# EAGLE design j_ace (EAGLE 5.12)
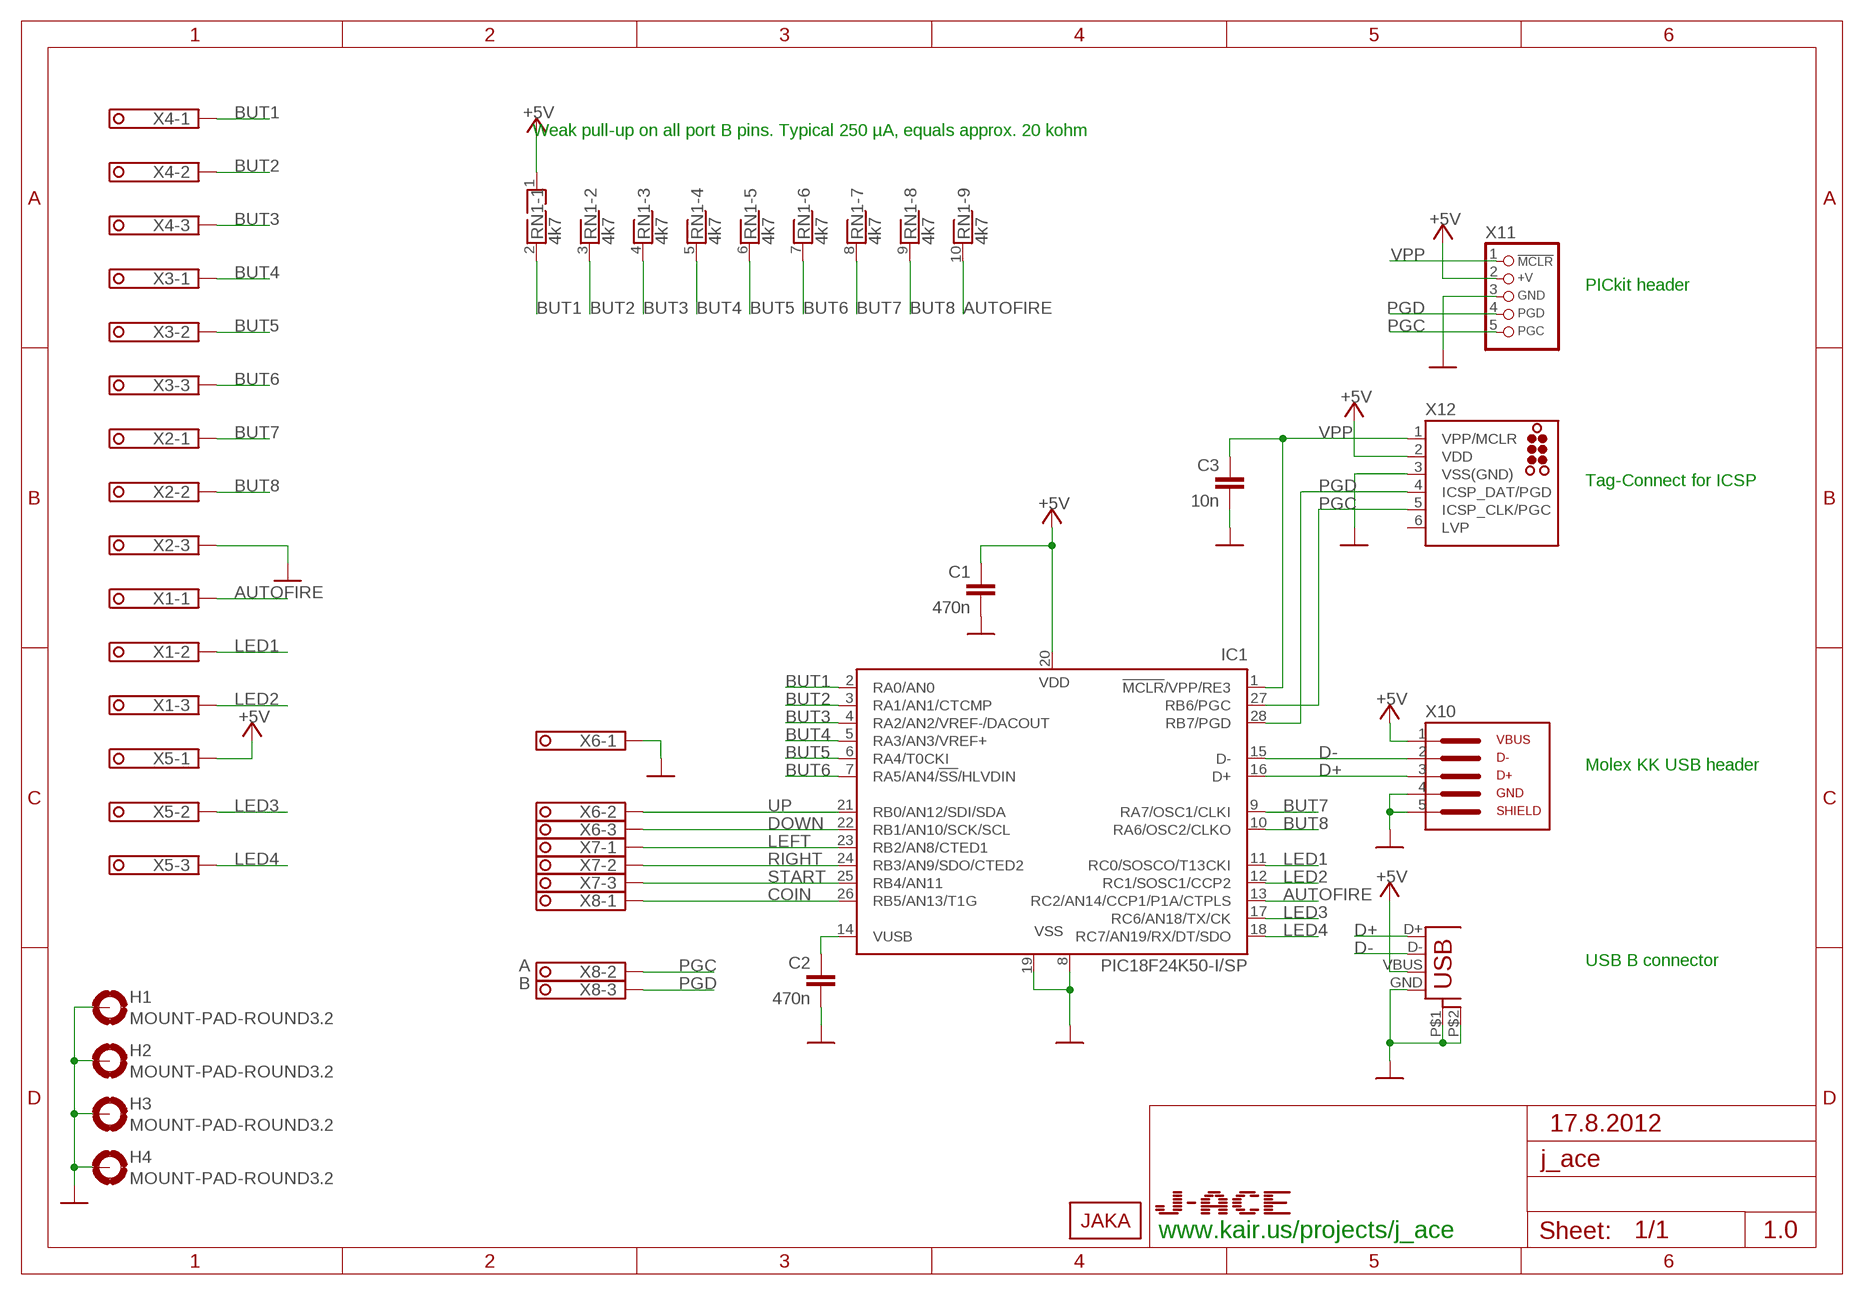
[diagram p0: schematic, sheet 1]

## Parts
C1  470n  C-EU050-024X044  [C050-024X044]
C2  470n  C-EU050-024X044  [C050-024X044]
C3  10n  C-EU050-024X044  [C050-024X044]
H1  MOUNT-PAD-ROUND3.2  [3,2-PAD]
H2  MOUNT-PAD-ROUND3.2  [3,2-PAD]
H3  MOUNT-PAD-ROUND3.2  [3,2-PAD]
H4  MOUNT-PAD-ROUND3.2  [3,2-PAD]
IC1  PIC18F24K50-I/SP  PIC18F2X50-I/SP  [DIL28-3]
LOGO1  J-ACE_LOGO_033  [J_ACE_LOGO_SILK_033]
RN1  4k7  RNX9  [RN-10]
U$1  JAKA_LOGO_SILK_NANO  [JAKA_SILK_NANO]
X1  1984620  [1984620]
X2  1984620  [1984620]
X3  1984620  [1984620]
X4  1984620  [1984620]
X5  1984620  [1984620]
X6  1984620  [1984620]
X7  1984620  [1984620]
X8  1984620  [1984620]
X9  USB_B_PTH  [SPARKFUN_USB-B-PTH]
X10  22-05-3051_USB_HEADER  [22-05-3051]
X11  CON_HEADER_PRG_PIC_ICSPSTAG  [HEADER_PRG_1X05_STAGGERED]
X12  TC2030-MCP-NL-JKA  [TC2030-MCP-NL-JKA]

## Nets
+5V [power]: C1.1 IC1.20(VDD) RN1.1 X5.1 X9.VBUS X10.1 X11.2(+V) X12.2(VDD)
AUTOFIRE: IC1.13(RC2/AN14/CCP1/P1A/CTPLS) RN1.10 X1.1
BUT1: IC1.2(RA0/AN0) RN1.2 X4.1
BUT2: IC1.3(RA1/AN1/CTCMP) RN1.3 X4.2
BUT3: IC1.4(RA2/AN2/VREF-/DACOUT) RN1.4 X4.3
BUT4: IC1.5(RA3/AN3/VREF+) RN1.5 X3.1
BUT5: IC1.6(RA4/T0CKI) RN1.6 X3.2
BUT6: IC1.7(RA5/AN4/!SS!/HLVDIN) RN1.7 X3.3
BUT7: IC1.9(RA7/OSC1/CLKI) RN1.8 X2.1
BUT8: IC1.10(RA6/OSC2/CLKO) RN1.9 X2.2
COIN: IC1.26(RB5/AN13/T1G) X8.1
D+ [USB]: IC1.16(D+) X9.D+ X10.3
D- [USB]: IC1.15(D-) X9.D- X10.2
DOWN: IC1.22(RB1/AN10/SCK/SCL) X6.3
GND [power]: C1.2 C2.2 C3.2 H1.B3,2(MOUNT) H2.B3,2(MOUNT) H3.B3,2(MOUNT) H4.B3,2(MOUNT) IC1.8(VSS) IC1.19(VSS) X2.3 X6.1 X9.GND X9.P$1(SHIELD) X9.P$2(SHIELD1) X10.4 X10.5 X11.3(GND) X12.3(VSS(GND))
LED1: IC1.11(RC0/SOSCO/T13CKI) X1.2
LED2: IC1.12(RC1/SOSC1/CCP2) X1.3
LED3: IC1.17(RC6/AN18/TX/CK) X5.2
LED4: IC1.18(RC7/AN19/RX/DT/SDO) X5.3
LEFT: IC1.23(RB2/AN8/CTED1) X7.1
N$3: C2.1 IC1.14(VUSB)
PGC: IC1.27(RB6/PGC) X8.2 X11.5(PGC) X12.5(ICSP_CLK/PGC)
PGD: IC1.28(RB7/PGD) X8.3 X11.4(PGD) X12.4(ICSP_DAT/PGD)
RIGHT: IC1.24(RB3/AN9/SDO/CTED2) X7.2
START: IC1.25(RB4/AN11) X7.3
UP: IC1.21(RB0/AN12/SDI/SDA) X6.2
VPP: C3.1 IC1.1(!MCLR!/VPP/RE3) X11.1(/MCLR) X12.1(VPP/MCLR)
Unconnected: X12.6(LVP)

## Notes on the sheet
- Weak pull-up on all port B pins. Typical 250 µA, equals approx. 20 kohm
- PICkit header
- Tag-Connect for ICSP
- Molex KK USB header
- USB B connector
- A
- B
- 17.8.2012
- www.kair.us/projects/j_ace | 1.0

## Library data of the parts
C1-C3 = dual_atari:C-EU: CAPACITOR, European symbol
H1-H4 = omat:MOUNT-PAD-ROUND: MOUNTING PAD, round
IC1 = dual_atari:PIC18F2X50
LOGO1 = omat:J-ACE_LOGO
RN1 = omat:RNX9: RESISTOR NETWORK
U$1 = dual_atari:JAKA_LOGO
X1-X8 = omat:1984620: MKDS 1/ 3-3,5 Printklemme Nennstrom: 10 A Bemessungsspannung: 160 V Raster: 3,5 mm Polzahl: 3 Montageart: Löten Anschlussart: Schraubanschluss Anschlussrichtung vom Leiter zur Platine: 0° Source: http://eshop.phoenixcontact.com .. 1751251.pdf; OC_FARNELL: unknown; OC_NEWARK: unknown
X9 = dual_atari:USB_B_PTH
X10 = omat:22-05-3051_USB_HEADER
X11 = omat:CON_HEADER_PRG_PIC_ICSP: 5-pin PIC In Circuit Serial Programming header
X12 = dual_atari:TC2030: TAG-CONNECT ISP Connector Manufacturer: Tag-Connect Cable for easy In-Circuit PCB Programming. Designed for Microchip ICD2, suitable for many others. Two variants - one "with legs" (for hads-free fit on PCB) and another "without legs" for quick programming. PADDescription 1MCLR/Vpp 2Vdd 3GND 4PGD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

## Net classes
0 default: width 0.3 mm, drill 0.6 mm, clearance 0.35 mm
1 USB: width 1.2 mm, drill 0.6 mm, clearance 0.35 mm
2 power: width 1 mm, drill 0.6 mm, clearance 0.35 mm

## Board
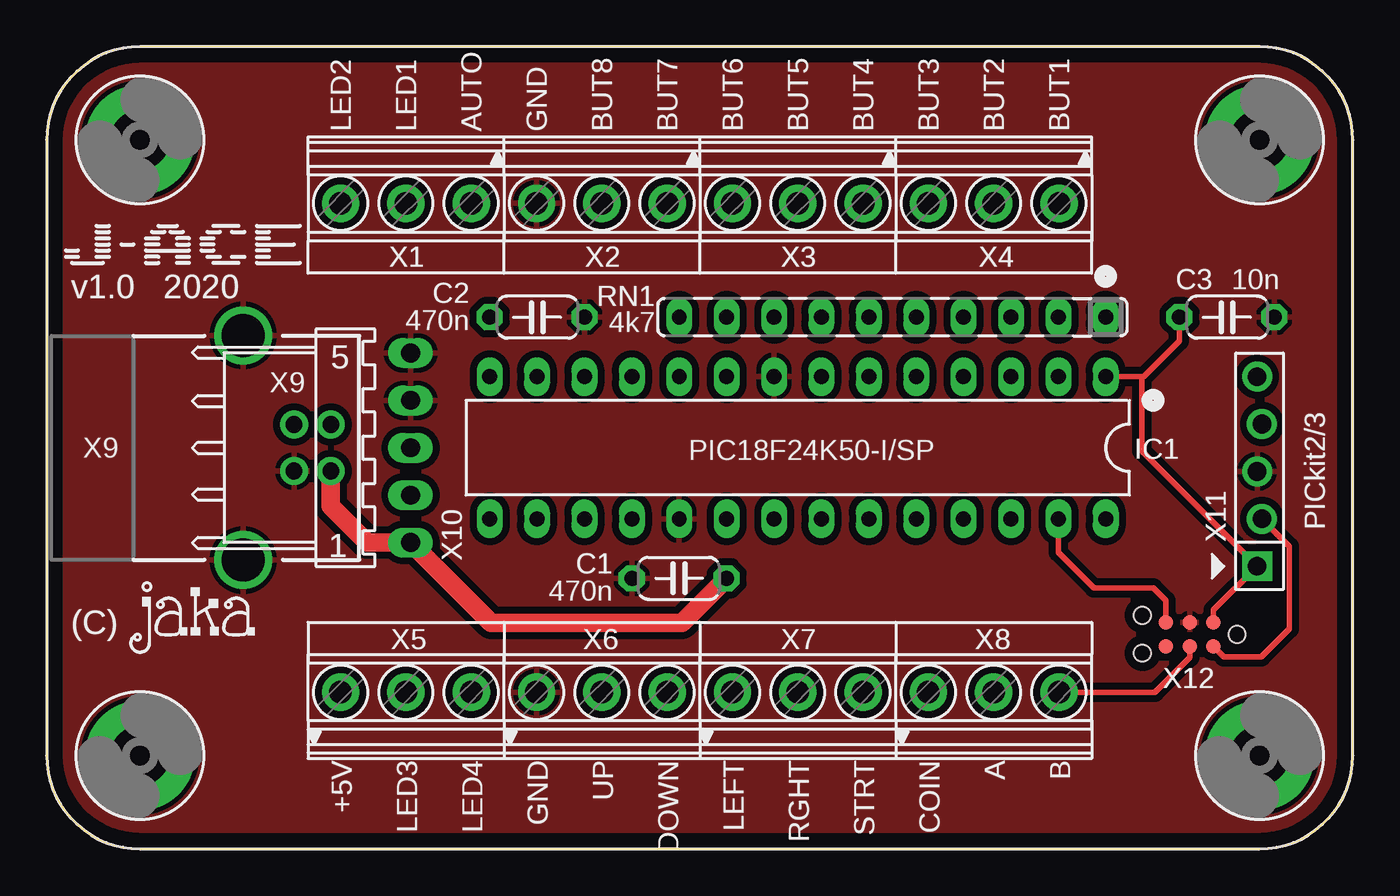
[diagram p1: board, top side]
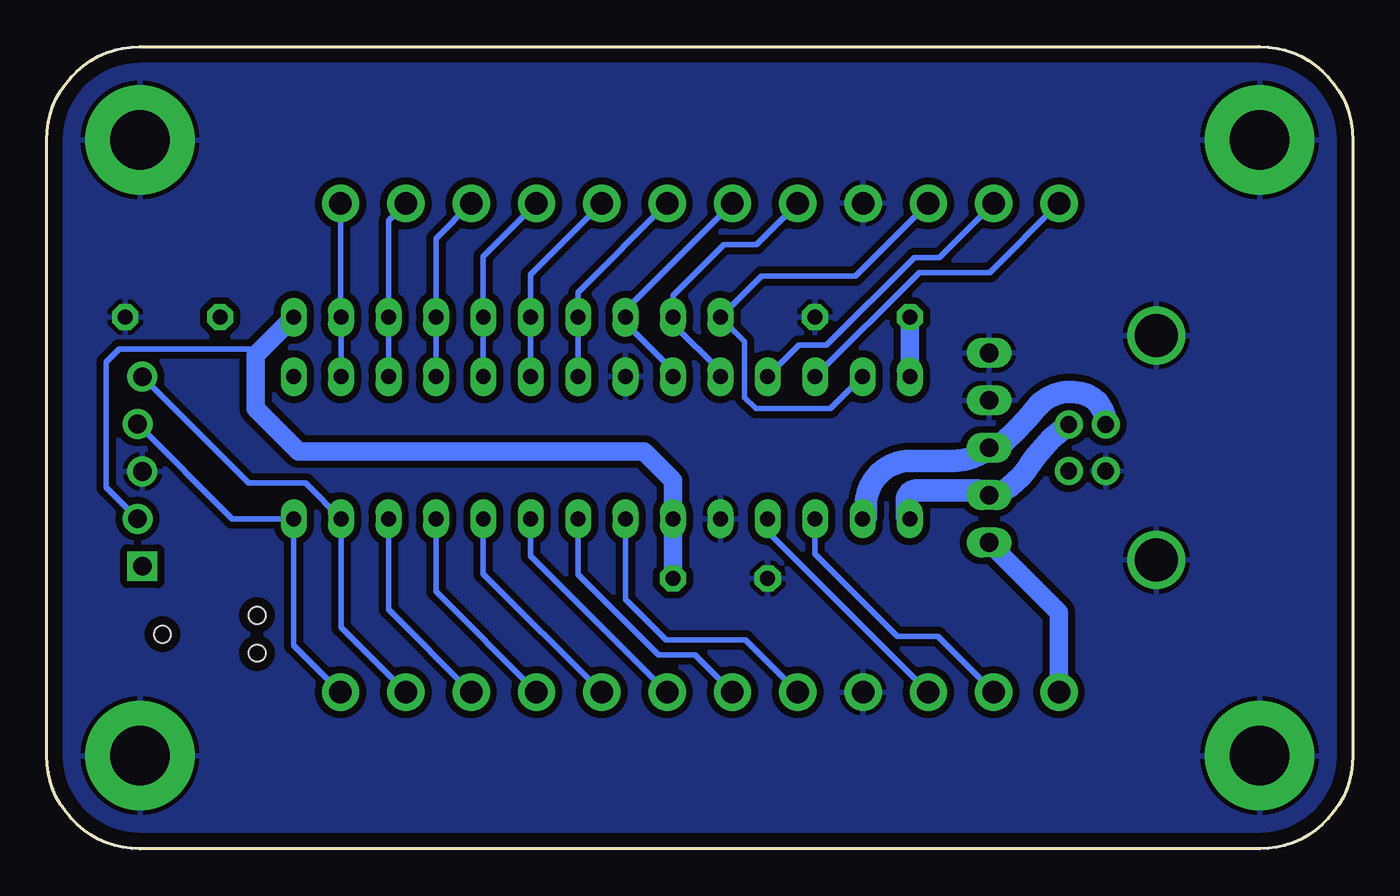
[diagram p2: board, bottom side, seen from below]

Size 70 x 43 mm. Coordinates in mm from the lower left corner, seen from the top.
Outline: 5,43 arc90 0,38 0,5 arc90 5,0 65,0 arc90 70,5 70,38 arc90 65,43 5,43
Copper layers (1*16): Top 0.035mm / dielectric 1.1mm / Bottom 0.035mm
Design rules "ITEADstudio_DRC *": minimum track width 0.3mm, minimum drill 0.6mm, track to track 0.35mm, track to pad 0.35mm, pad to pad 0.35mm, via to via 0.35mm, smd to smd 0mil, copper to edge 0.5mm, drill to drill 0.25mm, minimum pad ring 0.3mm, minimum via ring 0.3mm, stop-mask expansion 2mil, vias tented up to drill 100mil, thermal gap 10mil
tRestrict: area 3.6,3.6 to 6.4,6.4; area 63.6,3.6 to 66.4,6.4; area 3.6,36.6 to 6.4,39.4; area 63.6,36.6 to 66.4,39.4
bRestrict: area 3.6,3.6 to 6.4,6.4; area 63.6,3.6 to 66.4,6.4; area 3.6,36.6 to 6.4,39.4; area 63.6,36.6 to 66.4,39.4

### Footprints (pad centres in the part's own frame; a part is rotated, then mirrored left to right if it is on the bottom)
C050-024X044 = drill 0.8 octagon: 1 -2.54,0; 2 2.54,0
3,2-PAD = drill 3.2 pad 5.842 round: B3,2 0,0
DIL28-3 = drill 0.8 long: 1 -16.51,-3.81; 2 -13.97,-3.81; 3 -11.43,-3.81; 4 -8.89,-3.81; 5 -6.35,-3.81; 6 -3.81,-3.81; 7 -1.27,-3.81; 8 1.27,-3.81; 9 3.81,-3.81; 10 6.35,-3.81; 11 8.89,-3.81; 12 11.43,-3.81; 13 13.97,-3.81; 14 16.51,-3.81; 15 16.51,3.81; 16 13.97,3.81; 17 11.43,3.81; 18 8.89,3.81; 19 6.35,3.81; 20 3.81,3.81; 21 1.27,3.81; 22 -1.27,3.81; 23 -3.81,3.81; 24 -6.35,3.81; 25 -8.89,3.81; 26 -11.43,3.81; 27 -13.97,3.81; 28 -16.51,3.81
RN-10 = drill 0.8 long: 1 -11.43,0; 2 -8.89,0; 3 -6.35,0; 4 -3.81,0; 5 -1.27,0; 6 1.27,0; 7 3.81,0; 8 6.35,0; 9 8.89,0; 10 11.43,0
1984620 = drill 1.2 pad 2 round: 1 -3.5,-0.1; 2 0,-0.1; 3 3.5,-0.1
SPARKFUN_USB-B-PTH = drill 0.9 round: D+ 0,1.25; D- 1.981,1.25; GND 0,-1.25; VBUS 1.981,-1.25 | drill 2.3 round: P$1 -2.718,-6.02; P$2 -2.718,6.02
22-05-3051 = drill 1 long: 1 5.08,0; 2 2.54,0; 3 0,0; 4 -2.54,0; 5 -5.08,0
HEADER_PRG_1X05_STAGGERED = drill 1 square: 1 -5.08,0.127 | drill 1 round: 2 -2.54,-0.127; 3 0,0.127; 4 2.54,-0.127; 5 5.08,0.127
TC2030-MCP-NL-JKA = smd 0.787 x 0.787: 1 1.27,-0.635; 2 1.27,0.635; 3 2.54,-0.635; 4 2.54,0.635; 5 3.81,-0.635; 6 3.81,0.635 | hole 0.9: 0,0; 5.08,-1.016; 5.08,1.016

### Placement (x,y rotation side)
C1  33.9,14.5 180 top
C2  26.28,28.5 0 top
C3  63.25,28.5 0 top
H1  65,5 0 top
H2  5,5 0 top
H3  5,38 0 top
H4  65,38 0 top
IC1  40.25,21.5 180 top
LOGO1  7.3,32.4 0 top
RN1  45.33,28.5 180 top
U$1  7.8,12.4 0 top
U$2  [A5L-LOC]  not placed on the board
X1  19.25,34.5 180 top
X2  29.75,34.5 180 top
X3  40.25,34.5 180 top
X4  50.75,34.5 180 top
X5  19.25,8.5 0 top
X6  29.75,8.5 0 top
X7  40.25,8.5 0 top
X8  50.75,8.5 0 top
X9  13.25,21.5 0 top
X10  19.5,21.5 270 top
X11  65,20.23 90 top
X12  63.8,11.5 180 top

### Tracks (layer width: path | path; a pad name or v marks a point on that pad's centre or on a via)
+5V
  Top 0.3: X12.2 63.09,10.3 65.1,10.3 66.6,11.8 66.6,16.22 X11.2
  Top 1: X9.VBUS 15.23,18.37 17.18,16.42 X10.1 23.82,12.1 34.04,12.1 C1.1
  Bottom 0.3: X11.2 66.8,19.36 66.8,26.1 66.1,26.8 59.14,26.8 58.8,26.46
  Bottom 1: X10.1 15.75,12.67 X5.1 | C1.1 IC1.20 36.44,19.74 38,21.3 56.5,21.3 58.8,23.6 58.8,26.46 RN1.1
AUTOFIRE
  Bottom 0.3: IC1.13 27.99,23.6 32,23.6 32.6,24.2 32.6,27.2 RN1.10 31.7,30.7 26.65,30.7 X1.1
BUT1
  Bottom 0.3: IC1.2 54.22,28 | 54.22,28 RN1.2 | X4.1 54.25,28.03 54.22,28
BUT2
  Bottom 0.3: IC1.3 RN1.3 51.68,33.67 X4.2
BUT3
  Bottom 0.3: IC1.4 RN1.4 49.14,32.71 X4.3
BUT4
  Bottom 0.3: IC1.5 RN1.5 46.6,31.75 X3.1
BUT5
  Bottom 0.3: IC1.6 RN1.6 44.06,30.79 X3.2
BUT6
  Bottom 0.3: IC1.7 RN1.7 41.52,29.83 X3.3
BUT7
  Bottom 0.3: IC1.9 36.44,25.64 38.98,28.18 RN1.8 38.98,28.87 X2.1
BUT8
  Bottom 0.3: IC1.10 33.9,25.6 36.44,28.14 RN1.9 36.44,29.66 33.7,32.4 31.95,32.4 X2.2
COIN
  Bottom 0.3: IC1.26 51.68,12.83 X8.1
D+
  Bottom 1.2: IC1.16 arc-45 26.16,17.74 26.1,17.8 26.1,18.4 arc90 23.7,20.8 21.4,20.8 arc-40 X10.3 arc-45 18.7,21.8 arc-7 16.9,23.7 arc49 15.2,24.5 arc29 14,24.2 arc59 X9.D+
D-
  Bottom 1.2: IC1.15 arc90 23.9,17.85 23.9,18.7 arc90 23.4,19.2 20.1,19.2 arc-90 19.86,18.96 X10.2 arc-33 18.7,19.2 arc-23 17.3,20.6 arc21 X9.D-
DOWN
  Bottom 0.3: IC1.22 41.52,14.72 37.2,10.4 35.25,10.4 X6.3
GND
  pour Bottom (isolate 0.37): 1,5 arc90 5,1 65,1 arc90 69,5 69,38 arc90 65,42 5,42 arc90 1,38
  pour Top (isolate 0.37): 1,5 arc90 5,1 65,1 arc90 69,5 69,38 arc90 65,42 5,42 arc90 1,38
LED1
  Bottom 0.3: IC1.11 29.67,27 28.2,27 23.5,31.7 22.15,31.7 X1.2
LED2
  Bottom 0.3: IC1.12 23.23,30.9 19.45,30.9 X1.3
LED3
  Bottom 0.3: IC1.17 28.82,15.82 24.4,11.4 22.25,11.4 X5.2
LED4
  Bottom 0.3: IC1.18 31.36,17.01 X5.3
LEFT
  Bottom 0.3: IC1.23 44.06,15.71 X7.1
N$3
  Bottom 1: IC1.14 C2.1
PGC
  Top 0.3: X12.5 59.99,13.31 59.3,14 56.12,14 54.22,15.9 IC1.27
  Bottom 0.3: X8.2 54.22,11.87 IC1.27 56.13,19.6 59.16,19.6 X11.5
PGD
  Top 0.3: X12.4 61.26,10.26 59.4,8.4 X8.3
  Bottom 0.3: X8.3 56.76,10.91 IC1.28 60.05,17.69 X11.4
RIGHT
  Bottom 0.3: IC1.24 46.6,14.75 X7.2
START
  Bottom 0.3: IC1.25 49.14,13.79 X7.3
UP
  Bottom 0.3: IC1.21 38.98,13.38 36.8,11.2 32.55,11.2 X6.2
VPP
  Top 0.3: X12.1 62.53,12.81 X11.1 58.7,21.32 58.7,25.31 | C3.1 60.71,27.21 58.81,25.31 58.7,25.31 | 58.7,25.31 IC1.1

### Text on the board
tPlace: LED2 | LED1 | AUTO | GND | BUT8 | BUT7 | BUT6 | BUT5 | BUT4 | BUT3 | BUT2 | BUT1 | v1.0 2020 | PICkit2/3 | (C) | +5V | LED3 | LED4 | GND | UP | DOWN | LEFT | RGHT | STRT | COIN | A | B
tStop: WWW.KAIR.US
Document: Assembly drawing
_tsilk: LED2 | LED1 | AUTO | GND | BUT8 | BUT7 | BUT6 | BUT5 | BUT4 | BUT3 | BUT2 | BUT1 | X1 | X2 | X3 | X4 | v1.0 2020 | C2 | RN1 | C3 | 10n | 470n | 4k7 | 5 | X9 | PIC18F24K50-I/SP | IC1 | 1 | PICkit2/3 | C1 | X11 | X10 | 470n | (C) | X5 | X6 | X7 | X8 | X12 | +5V | LED3 | LED4 | GND | UP | DOWN | LEFT | RGHT | STRT | COIN | A | B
